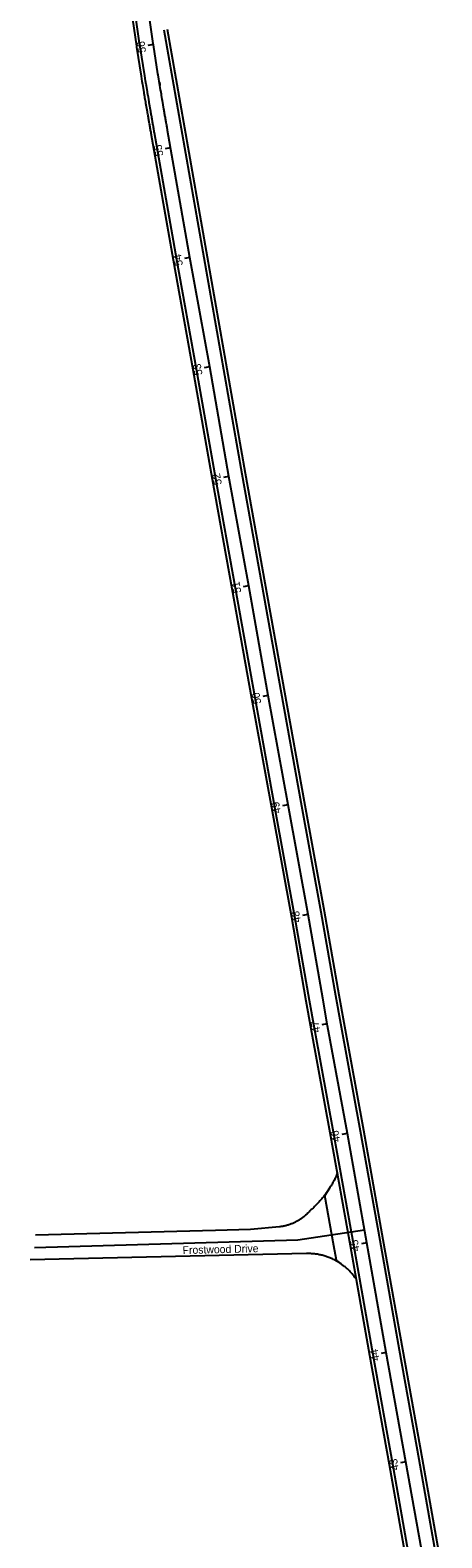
# Model space of a CAD drawing. Extents: x 2318076 to 2324211, y 613525 to 629939.
# Drawn here: x 2318533 to 2318903, y 619162 to 620517 of the extents above; entities that cross this region are included whole.
import ezdxf

# ---------------------------------------------------------------- set-up
doc = ezdxf.new("R2010")
doc.units = 0
for name, color, linetype in [('GE_P_CL_50', 7, 'Continuous'), ('GE_X_CL_50', 7, 'Continuous'), ('PV_P_EOP', 7, 'Continuous'), ('PV_P_Shoulder', 7, 'Continuous'), ('RS_Raster1', 7, 'Continuous')]:
    doc.layers.add(name, color=color, linetype=linetype)

msp = doc.modelspace()

# ---------------------------------------------------------------- linework, layer by layer
at = {"layer": 'GE_P_CL_50'}
for p, q in [((2318643.6, 620503.8), (2318638.7, 620503.1)), ((2318659.1, 620411), (2318654.2, 620410.1)), ((2318676.6, 620312.5), (2318671.7, 620311.6)), ((2318694.2, 620214.1), (2318689.3, 620213.2)), ((2318711.5, 620115.6), (2318706.6, 620114.7)), ((2318729.3, 620017.2), (2318724.4, 620016.3)), ((2318746.9, 619918.8), (2318742, 619917.9)), ((2318764.6, 619820.3), (2318759.7, 619819.4)), ((2318782.6, 619722), (2318777.7, 619721.1)), ((2318799.9, 619623.5), (2318795, 619622.6)), ((2318817.9, 619525.1), (2318813, 619524.2)), ((2318835.5, 619426.7), (2318830.5, 619425.8)), ((2318853.2, 619328.2), (2318848.3, 619327.3)), ((2318870.6, 619229.8), (2318865.7, 619228.9))]:
    msp.add_line(p, q, dxfattribs=at)
msp.add_lwpolyline([(2318888, 619131.3), (2318870.5, 619229.8), (2318852.9, 619328.2), (2318835.5, 619426.7), (2318817.9, 619525.1), (2318800.2, 619621.8), (2318795.8, 619646.7), (2318782.6, 619722), (2318764.6, 619820.3), (2318746.9, 619918.8), (2318729.3, 620017.2), (2318711.5, 620115.6), (2318694.2, 620214.1), (2318676.5, 620312.5), (2318656.4, 620426.6), (2318656.2, 620427.6), (2318656.1, 620428.6), (2318655.9, 620429.5), (2318655.7, 620430.5), (2318655.6, 620431.4), (2318655.4, 620432.4), (2318655.2, 620433.4), (2318655.1, 620434.3), (2318654.9, 620435.3), (2318654.7, 620436.2), (2318654.5, 620437.2), (2318654.4, 620438.2), (2318654.2, 620439.1), (2318654, 620440.1), (2318653.9, 620441.1), (2318653.7, 620442), (2318653.5, 620443), (2318653.4, 620443.9), (2318653.2, 620444.9), (2318653, 620445.9), (2318651.7, 620453.6), (2318651.6, 620454.5), (2318650.9, 620458.4), (2318650.8, 620459.3), (2318650.3, 620462.2), (2318650.1, 620463.2), (2318649.2, 620469), (2318649, 620469.9), (2318649.3, 620468), (2318649.5, 620467), (2318647.9, 620476.7), (2318647.7, 620477.6), (2318643.7, 620503.7), (2318643.5, 620504.7), (2318636.8, 620551)], dxfattribs=at)
at = {"layer": 'GE_X_CL_50'}
msp.add_lwpolyline([(2318536.7, 619422.6), (2318773.4, 619429.3), (2318833.3, 619438.5)], dxfattribs=at)
at = {"layer": 'PV_P_EOP'}
for points in [[(2318876.2, 619129.2), (2318858.7, 619227.7), (2318841, 619326.1), (2318823.6, 619424.6), (2318806.1, 619523), (2318788.4, 619619.6), (2318784, 619644.6), (2318770.8, 619719.9), (2318752.8, 619818.2), (2318735.1, 619916.6), (2318717.5, 620015.1), (2318699.7, 620113.5), (2318682.4, 620212), (2318664.7, 620310.4), (2318644.6, 620424.5), (2318644.4, 620425.5), (2318644.3, 620426.4), (2318644.1, 620427.4), (2318643.9, 620428.4), (2318643.7, 620429.3), (2318643.6, 620430.3), (2318643.4, 620431.3), (2318643.2, 620432.2), (2318643.1, 620433.2), (2318642.9, 620434.2), (2318642.7, 620435.1), (2318642.6, 620436.1), (2318642.4, 620437.1), (2318642.2, 620438), (2318642.1, 620439), (2318641.9, 620440), (2318641.7, 620440.9), (2318641.6, 620441.9), (2318641.4, 620442.9), (2318641.2, 620443.8), (2318639.9, 620451.6), (2318639.7, 620452.5), (2318639.1, 620456.4), (2318638.9, 620457.4), (2318638.4, 620460.3), (2318638.3, 620461.2), (2318637.3, 620467), (2318637.2, 620468), (2318636.6, 620471.2), (2318635.9, 620475.8), (2318631.8, 620501.9), (2318631.6, 620502.9), (2318624.9, 620549.4)], [(2318899.8, 619133.4), (2318882.3, 619231.9), (2318864.7, 619330.3), (2318847.3, 619428.8), (2318829.7, 619527.2), (2318812.1, 619623.9), (2318807.6, 619648.8), (2318794.4, 619724.1), (2318776.5, 619822.5), (2318758.8, 619920.9), (2318741.1, 620019.3), (2318723.4, 620117.7), (2318653.3, 620516.8)], [(2318809, 619489.6), (2318808.9, 619489.2), (2318808.5, 619488.4), (2318808.2, 619487.6), (2318807.8, 619486.7), (2318807.4, 619485.9), (2318807, 619485.1), (2318806.7, 619484.3), (2318806.3, 619483.5), (2318805.9, 619482.7), (2318805.4, 619481.9), (2318805, 619481.2), (2318804.6, 619480.4), (2318804.2, 619479.6), (2318803.7, 619478.8), (2318803.3, 619478.1), (2318802.8, 619477.3), (2318802.3, 619476.5), (2318801.9, 619475.8), (2318797.6, 619469.2)], [(2318808, 619411.1), (2318805.7, 619424), (2318797.6, 619469.2)], [(2318825.9, 619394.4), (2318824.4, 619396), (2318823.9, 619396.7), (2318823.3, 619397.4), (2318822.8, 619398.1), (2318822.2, 619398.8), (2318821.6, 619399.5), (2318821, 619400.2), (2318820.4, 619400.8), (2318819.8, 619401.5), (2318819.1, 619402.1), (2318818.5, 619402.7), (2318817.9, 619403.3), (2318817.2, 619403.9), (2318816.5, 619404.5), (2318815.8, 619405.1), (2318815.2, 619405.6), (2318814.5, 619406.2), (2318808, 619411.1)]]:
    msp.add_lwpolyline(points, dxfattribs=at)
at = {"layer": 'PV_P_Shoulder'}
for points in [[(2318873.2, 619128.7), (2318855.7, 619227.1), (2318838.1, 619325.6), (2318820.7, 619424), (2318803.1, 619522.4), (2318785.5, 619619.1), (2318781, 619644.1), (2318767.9, 619719.3), (2318749.9, 619817.7), (2318732.2, 619916.1), (2318714.5, 620014.5), (2318696.8, 620113), (2318679.5, 620211.5), (2318661.7, 620309.9), (2318641.7, 620424), (2318641.5, 620425), (2318641.3, 620425.9), (2318641.1, 620426.9), (2318641, 620427.9), (2318640.8, 620428.8), (2318640.6, 620429.8), (2318640.5, 620430.8), (2318640.3, 620431.7), (2318640.1, 620432.7), (2318639.9, 620433.7), (2318639.8, 620434.6), (2318639.6, 620435.6), (2318639.4, 620436.6), (2318639.3, 620437.5), (2318639.1, 620438.5), (2318638.9, 620439.5), (2318638.8, 620440.4), (2318638.6, 620441.4), (2318638.4, 620442.4), (2318638.3, 620443.3), (2318636.9, 620451), (2318636.8, 620452), (2318636.1, 620455.9), (2318636, 620456.9), (2318635.5, 620459.8), (2318635.3, 620460.7), (2318634.4, 620466.5), (2318634.2, 620467.5), (2318633.7, 620470.7), (2318632.9, 620475.3), (2318628.8, 620501.4), (2318628.7, 620502.5), (2318622, 620549)], [(2318902.8, 619133.9), (2318885.3, 619232.4), (2318867.6, 619330.8), (2318850.2, 619429.3), (2318832.7, 619527.8), (2318815, 619624.4), (2318810.6, 619649.3), (2318797.4, 619724.6), (2318779.4, 619823), (2318761.7, 619921.4), (2318744, 620019.8), (2318726.3, 620118.2), (2318656.3, 620517.3)]]:
    msp.add_lwpolyline(points, dxfattribs=at)
at = {"layer": 'RS_Raster1'}
for p, q in [((2318756.9, 619441.1), (2318730.8, 619438.8)), ((2318781.2, 619417), (2318532.9, 619411.4))]:
    msp.add_line(p, q, dxfattribs=at)
for points in [[(2318809, 619489.6), (2318808.9, 619489.2), (2318808.5, 619488.4), (2318808.2, 619487.6), (2318807.8, 619486.7), (2318807.4, 619485.9), (2318807, 619485.1), (2318806.7, 619484.3), (2318806.3, 619483.5), (2318805.9, 619482.7), (2318805.4, 619481.9), (2318805, 619481.2), (2318804.6, 619480.4), (2318804.2, 619479.6), (2318803.7, 619478.8), (2318803.3, 619478.1), (2318802.8, 619477.3), (2318802.3, 619476.5), (2318801.9, 619475.8), (2318801.4, 619475), (2318800.9, 619474.3), (2318800.4, 619473.5), (2318799.9, 619472.8), (2318799.4, 619472.1), (2318798.9, 619471.3), (2318798.4, 619470.6), (2318797.8, 619469.9), (2318797.3, 619469.2), (2318796.7, 619468.5), (2318796.2, 619467.8), (2318795.6, 619467.1), (2318795.1, 619466.4), (2318794.5, 619465.7), (2318793.9, 619465.1), (2318793.3, 619464.4), (2318792.7, 619463.7), (2318792.1, 619463.1), (2318791.5, 619462.4), (2318790.9, 619461.8), (2318790.3, 619461.1), (2318789.6, 619460.5), (2318789, 619459.9), (2318788.4, 619459.3), (2318787.7, 619458.6), (2318787.1, 619458), (2318786.4, 619457.4), (2318785.8, 619456.8), (2318785.1, 619456.3), (2318784.4, 619455.7)], [(2318784.4, 619455.7), (2318783.9, 619455.1), (2318783.5, 619454.6), (2318783, 619454.1), (2318782.5, 619453.5), (2318781.9, 619453), (2318781.4, 619452.5), (2318780.9, 619452), (2318780.4, 619451.5), (2318779.8, 619451), (2318779.3, 619450.6), (2318778.7, 619450.1), (2318778.1, 619449.7), (2318777.6, 619449.2), (2318777, 619448.8), (2318776.4, 619448.4), (2318775.8, 619448), (2318775.2, 619447.6), (2318774.6, 619447.2), (2318773.9, 619446.8), (2318773.3, 619446.5), (2318772.7, 619446.1), (2318772, 619445.8), (2318771.4, 619445.4), (2318770.7, 619445.1), (2318770.1, 619444.8), (2318769.4, 619444.5), (2318768.8, 619444.2), (2318768.1, 619443.9), (2318767.4, 619443.7), (2318766.7, 619443.4), (2318766.1, 619443.2), (2318765.4, 619442.9), (2318764.7, 619442.7), (2318764, 619442.5), (2318763.3, 619442.3), (2318762.6, 619442.1), (2318761.9, 619442), (2318761.2, 619441.8), (2318760.5, 619441.7), (2318759.8, 619441.5), (2318759, 619441.4), (2318758.3, 619441.3), (2318757.6, 619441.2), (2318756.9, 619441.1)], [(2318730.8, 619438.8), (2318699.3, 619437.7), (2318537.7, 619433.6)], [(2318825.9, 619394.4), (2318824.4, 619396), (2318823.9, 619396.7), (2318823.3, 619397.4), (2318822.8, 619398.1), (2318822.2, 619398.8), (2318821.6, 619399.5), (2318821, 619400.2), (2318820.4, 619400.8), (2318819.8, 619401.5), (2318819.1, 619402.1), (2318818.5, 619402.7), (2318817.9, 619403.3), (2318817.2, 619403.9), (2318816.5, 619404.5), (2318815.8, 619405.1), (2318815.2, 619405.6), (2318814.5, 619406.2), (2318813.7, 619406.7), (2318813, 619407.3), (2318812.3, 619407.8), (2318811.6, 619408.3), (2318810.8, 619408.8), (2318810.1, 619409.2), (2318809.3, 619409.7), (2318808.5, 619410.1), (2318807.8, 619410.6), (2318807, 619411), (2318806.2, 619411.4), (2318805.4, 619411.8), (2318804.6, 619412.2), (2318803.8, 619412.6), (2318802.9, 619412.9), (2318802.1, 619413.3), (2318801.3, 619413.6), (2318800.5, 619413.9), (2318799.6, 619414.2), (2318798.8, 619414.5), (2318797.9, 619414.7), (2318797.1, 619415), (2318796.2, 619415.2), (2318795.3, 619415.5), (2318794.5, 619415.7), (2318793.6, 619415.9), (2318792.7, 619416), (2318791.9, 619416.2), (2318791, 619416.4), (2318790.1, 619416.5), (2318789.2, 619416.6), (2318788.3, 619416.7), (2318787.4, 619416.8), (2318786.6, 619416.9), (2318785.7, 619416.9), (2318784.8, 619417), (2318783.9, 619417), (2318783, 619417), (2318782.1, 619417), (2318781.2, 619417)]]:
    msp.add_lwpolyline(points, dxfattribs=at)

# ---------------------------------------------------------------- texts
at = {"layer": 'GE_P_CL_50'}
for s, rotation, p in [('56', 98.664, (2318637.1, 620497)), ('55', 99.8658, (2318652.7, 620404.1)), ('54', 100.3286, (2318670.2, 620305.6)), ('53', 99.7541, (2318687.8, 620207.2)), ('52', 100.2644, (2318705.2, 620108.7)), ('51', 100.1654, (2318722.7, 620011.4)), ('50', 100.1542, (2318740.6, 619911.7)), ('49', 100.3914, (2318758.3, 619813.4)), ('48', 99.9262, (2318776.2, 619715.2)), ('47', 100.1064, (2318793.6, 619616.4)), ('46', 100.7349, (2318811.6, 619518)), ('Frostwood Drive', 1.4386, (2318670, 619416.6)), ('45', 99.7749, (2318829, 619419.7)), ('44', 100.5044, (2318846.9, 619321.3)), ('43', 99.8567, (2318864.2, 619222.8))]:
    msp.add_text(s, height=7, rotation=rotation, dxfattribs=at).set_placement(p)

doc.saveas('drawing.dxf')
